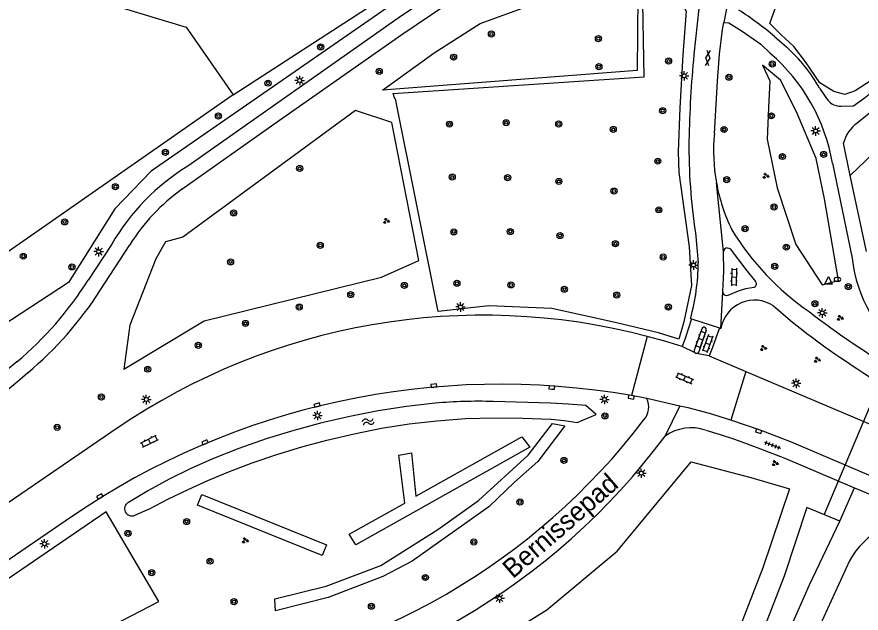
# Model space of a CAD drawing. Extents: x 131000 to 133013, y 393000 to 396501.
# Drawn here: x 131381.1 to 131491.8, y 394809 to 394887.2 of the extents above; entities that cross this region are included whole.
import ezdxf

# ---------------------------------------------------------------- set-up
doc = ezdxf.new("R2010")
doc.units = 0
for name, color, linetype in [('gg-afsc-erfafscheiding', 7, 'Continuous'), ('gg-afsc-hekwerk', 7, 'Continuous'), ('gg-anno-openbare ruimte label', 7, 'Continuous'), ('gg-knt-bovenkant onderkant talud', 7, 'Continuous'), ('gg-knt-verharding', 7, 'Continuous'), ('gg-knt-verharding nz', 7, 'Continuous'), ('gg-kntw-bovenkant insteek waterloop', 7, 'Continuous'), ('gg-kwrk-duiker nz buis', 7, 'Continuous'), ('gt-grn-groengrens', 7, 'Continuous'), ('gt-grn-vlakafsluiter', 7, 'Continuous'), ('gt-grn-weggrens', 7, 'Continuous'), ('gt-symb-boom', 7, 'Continuous'), ('gt-symb-brandkraan', 7, 'Continuous'), ('gt-symb-gesloten verharding', 7, 'Continuous'), ('gt-symb-groenvak', 7, 'Continuous'), ('gt-symb-klinker verharding', 7, 'Continuous'), ('gt-symb-kolk', 7, 'Continuous'), ('gt-symb-lichtmast', 7, 'Continuous'), ('gt-symb-tegel verharding', 7, 'Continuous'), ('gt-symb-waterafsluiter', 7, 'Continuous'), ('gt-symb-watersymbool', 7, 'Continuous')]:
    doc.layers.add(name, color=color, linetype=linetype)

# ---------------------------------------------------------------- blocks, each defined once
blk = doc.blocks.new('gt0-BOOM')
at = {"layer": 'gt-symb-boom'}
for radius in [0.4, 0.2]:
    blk.add_circle((0, 0), radius, dxfattribs=at)
blk = doc.blocks.new('gt0-LMAST')
at = {"layer": 'gt-symb-lichtmast'}
for p, q in [((-0.18, 0.17), (-0.45, 0.44)), ((-0.01, 0.25), (-0.01, 0.62)), ((0.17, 0.17), (0.44, 0.44)), ((-0.26, 0), (-0.63, 0)), ((-0.18, -0.18), (-0.45, -0.45)), ((-0.01, -0.25), (-0.01, -0.63)), ((0.44, -0.45), (0.17, -0.18)), ((0.24, 0), (0.62, 0))]:
    blk.add_line(p, q, dxfattribs=at)
blk.add_circle((-0.01, 0), 0.25, dxfattribs=at)
blk = doc.blocks.new('gt0-GESVH1')
at = {"layer": 'gt-symb-gesloten verharding'}
for p, q in [((-0.99, -0.26), (0.01, 0.24)), ((0.01, -0.26), (-0.99, 0.24)), ((0.01, 0.24), (1.01, -0.26)), ((1.01, 0.24), (0.01, -0.26))]:
    blk.add_line(p, q, dxfattribs=at)
blk = doc.blocks.new('gt0-GRVAK')
at = {"layer": 'gt-symb-groenvak'}
for p, q in [((-0.11, 0.19), (-0.23, 0.24)), ((-0.18, 0.15), (0.09, 0.15)), ((-0.09, 0.21), (-0.16, 0.32)), ((-0.05, 0.21), (-0.05, 0.39)), ((0, 0.21), (0.06, 0.32)), ((0.02, 0.19), (0.13, 0.24)), ((0.26, -0.05), (0.2, 0.06)), ((0.31, -0.05), (0.31, 0.13)), ((0.35, -0.05), (0.41, 0.06)), ((-0.24, -0.23), (-0.36, -0.18)), ((-0.32, -0.26), (-0.05, -0.26)), ((-0.23, -0.21), (-0.29, -0.09)), ((-0.18, -0.2), (-0.18, -0.02)), ((-0.14, -0.21), (-0.07, -0.09)), ((-0.12, -0.23), (0, -0.18)), ((0.24, -0.07), (0.12, -0.02)), ((0.17, -0.11), (0.44, -0.11)), ((0.37, -0.07), (0.49, -0.02))]:
    blk.add_line(p, q, dxfattribs=at)
blk = doc.blocks.new('gt0-KOLK')
at = {"layer": 'gt-symb-kolk'}
blk.add_lwpolyline([(0, 0), (0.37, 0), (0.37, 0.4), (-0.38, 0.4), (-0.38, 0), (0, 0)], dxfattribs=at)
blk = doc.blocks.new('gt0-KL1')
at = {"layer": 'gt-symb-klinker verharding'}
for p, q in [((-1.15, 0.3), (1.15, 0.3)), ((-1, -0.3), (-1, 0.3)), ((-0.5, 0.3), (-0.5, 0.45)), ((0, -0.3), (0, 0.3)), ((0.5, 0.3), (0.5, 0.45)), ((1, -0.3), (1, 0.3)), ((-1.15, -0.3), (1.15, -0.3)), ((-0.5, -0.45), (-0.5, -0.3)), ((0.5, -0.45), (0.5, -0.3))]:
    blk.add_line(p, q, dxfattribs=at)
blk = doc.blocks.new('gt0-WAFSL')
at = {"layer": 'gt-symb-waterafsluiter'}
for p, q in [((-0.5, -0.33), (0, 0.67)), ((0, 0.67), (0.5, -0.33)), ((0.5, -0.33), (-0.5, -0.33))]:
    blk.add_line(p, q, dxfattribs=at)
blk = doc.blocks.new('gt0-BR')
at = {"layer": 'gt-symb-brandkraan'}
for centre, radius, start, end in [((-0.24, 0), 0.206, 107.5669, 252.4331), ((0.6, -2.66), 3, 106.892, 107.5669), ((0, -0.69), 0.938, 73.108, 106.892), ((-0.6, -2.66), 3, 72.4331, 73.108), ((0.24, 0), 0.206, 287.567, 72.4331), ((0.6, 2.66), 3, 252.4331, 253.108), ((0, 0.69), 0.938, 253.108, 286.8921), ((-0.6, 2.66), 3, 286.8921, 287.567)]:
    blk.add_arc(centre, radius, start, end, dxfattribs=at)
blk = doc.blocks.new('gt0-TEG1')
at = {"layer": 'gt-symb-tegel verharding'}
for p, q in [((-1.12, 0), (1.12, 0)), ((-0.9, -0.25), (-0.9, 0.25)), ((-0.45, -0.25), (-0.45, 0.25)), ((0, -0.25), (0, 0.25)), ((0.45, -0.25), (0.45, 0.25)), ((0.9, -0.25), (0.9, 0.25))]:
    blk.add_line(p, q, dxfattribs=at)
blk = doc.blocks.new('gt0-WA')
at = {"layer": 'gt-symb-watersymbool'}
for centre, start, end in [((-0.32, 0.02), 28.0725, 151.9275), ((0.43, 0.42), 208.0725, 331.9275), ((-0.32, -0.43), 28.0725, 151.9275), ((0.43, -0.03), 208.0725, 331.9275)]:
    blk.add_arc(centre, 0.425, start, end, dxfattribs=at)

msp = doc.modelspace()

# ---------------------------------------------------------------- linework, layer by layer
at = {"layer": 'gg-afsc-erfafscheiding'}
msp.add_lwpolyline([(131382.74, 394892.07), (131403.32, 394885.82), (131409.48, 394876.97)], dxfattribs=at)
at = {"layer": 'gg-afsc-hekwerk'}
for points in [[(131409.48, 394876.97), (131433.9, 394892.83), (131436.29, 394894.28), (131439.98, 394898.11), (131439.63, 394901.76), (131437.93, 394908.16)], [(131383.91, 394859.19), (131409.38, 394876.91), (131409.48, 394876.97)]]:
    msp.add_lwpolyline(points, dxfattribs=at)
at = {"layer": 'gg-knt-bovenkant onderkant talud'}
msp.add_line((131490.29, 394815.9), (131481.29, 394796.36), dxfattribs=at)
msp.add_arc((131499.9, 394810.49), 11.03, 88.3052, 150.6017, dxfattribs=at)
at = {"layer": 'gg-knt-verharding'}
for p, q in [((131470.52, 394888.26), (131469.88, 394882.22)), ((131480.47, 394884.58), (131482.05, 394883.2)), ((131486.37, 394877.83), (131487.1, 394876.74)), ((131489.2, 394875.47), (131490.8, 394875.51)), ((131493.76, 394875.23), (131491.29, 394873.26)), ((131490.39, 394866.39), (131489.5, 394870.6)), ((131488.06, 394867.99), (131490.62, 394855.54)), ((131492.49, 394856.41), (131490.39, 394866.39)), ((131470.09, 394858.85), (131470.46, 394854.93)), ((131393.57, 394857.38), (131390.48, 394852.68)), ((131392.03, 394851.28), (131395.93, 394857.31)), ((131480.34, 394849.3), (131482.56, 394847.38)), ((131469.59, 394847.59), (131468.77, 394845.17)), ((131469.43, 394847.64), (131469.59, 394847.59)), ((131469.59, 394847.59), (131473.24, 394846.41)), ((131473.24, 394846.41), (131472.32, 394843.82)), ((131473.24, 394846.41), (131473.43, 394846.35)), ((131463.78, 394845.3), (131461.7, 394837.53)), ((131468.77, 394845.17), (131468.34, 394843.97)), ((131472.32, 394843.82), (131471.9, 394842.74)), ((131470.04, 394843.13), (131470.2, 394843.07)), ((131471.9, 394842.74), (131476.68, 394840.71)), ((131381.14, 394841.97), (131375.18, 394837.09)), ((131476.68, 394840.71), (131474.71, 394834.34)), ((131463.71, 394837.16), (131461.7, 394837.53)), ((131468.06, 394836.17), (131463.71, 394837.16)), ((131466.12, 394832.24), (131468.06, 394836.17)), ((131394.29, 394833.26), (131300.6, 394769.27)), ((131490.93, 394825.46), (131500.23, 394821.51)), ((131388.31, 394821.67), (131304.05, 394764.12))]:
    msp.add_line(p, q, dxfattribs=at)
for points in [[(131436.71, 394890.81), (131431.13, 394887), (131403.53, 394867.61)], [(131402.78, 394864.57), (131415.57, 394873.63), (131431.62, 394884.85), (131439.27, 394890.04)], [(131472.57, 394871.87), (131472.97, 394878.74), (131473.24, 394882.28), (131473.62, 394885.53), (131473.79, 394886.44)], [(131473.79, 394886.44), (131474.46, 394886.4), (131476.22, 394885.31), (131478.65, 394883.58), (131479.91, 394882.39)], [(131474.25, 394856.91), (131474.46, 394856.86), (131474.65, 394856.75), (131476.7, 394854.05), (131477.97, 394852.5)], [(131473.69, 394851.17), (131473.8, 394853.78), (131473.75, 394856.38)], [(131477.89, 394851.78), (131477.77, 394851.71), (131476.63, 394851.51), (131475.67, 394851.24), (131474.34, 394850.65), (131474.16, 394850.63), (131473.99, 394850.67), (131473.85, 394850.76), (131473.72, 394850.95), (131473.69, 394851.17)], [(131470.93, 394846.3), (131469.93, 394843.47), (131469.93, 394843.28), (131470.04, 394843.13)], [(131471.49, 394846.12), (131470.52, 394843.28), (131470.4, 394843.12), (131470.2, 394843.07)], [(131468.34, 394843.97), (131466.07, 394844.67), (131463.78, 394845.3)], [(131378.35, 394837.04), (131381.54, 394839.65), (131382.59, 394840.55)], [(131476.68, 394840.71), (131510.2, 394826.5), (131512.36, 394825.7)], [(131474.71, 394834.34), (131471.93, 394835.18), (131469.12, 394835.93), (131468.06, 394836.17)], [(131509.6, 394819.96), (131482.66, 394831.43), (131478.72, 394832.97), (131474.71, 394834.34)], [(131471.43, 394833.02), (131473.35, 394832.45), (131475.23, 394831.82), (131478.07, 394830.79), (131481.79, 394829.34), (131490.93, 394825.46)]]:
    msp.add_lwpolyline(points, dxfattribs=at)
for centre, radius, start, end in [((131452.42, 394851.63), 43.27, 49.5822, 57.3432), ((131473.3, 394900.95), 30.88, 304.5159, 333.2522), ((131463.78, 394863.76), 24.64, 9.898, 49.1217), ((131467.54, 394867.1), 21.67, 29.6679, 47.9583), ((131621.09, 394867.8), 151.89, 174.5512, 178.8182), ((131489.13, 394877.71), 2.25, 205.5536, 271.9602), ((131494.09, 394869.44), 4.74, 126.341, 165.8723), ((131496.11, 394869.63), 23.65, 174.5726, 190.271), ((131545.54, 394870.28), 76.31, 179.5131, 188.6136), ((131419.05, 394842.54), 29.48, 121.7506, 149.7763), ((131496.1, 394869.63), 23.64, 190.2855, 205.9898), ((131417.7, 394843.63), 25.71, 125.4665, 147.8465), ((131505.52, 394878.1), 35.99, 211.5418, 235.2011), ((131474.29, 394856.38), 0.534, 93.9828, 179.9134), ((131443.23, 394855.03), 27.22, 344.2568, 359.8021), ((131509.86, 394857.85), 19.38, 186.833, 232.0434), ((131351.71, 394877.05), 45.79, 309.9989, 327.8448), ((131477.57, 394852.18), 0.511, 308.3148, 38.7083), ((131351.71, 394877.22), 47.95, 310.0985, 327.2461), ((131477.85, 394845.57), 4.48, 56.3437, 170.0595), ((131442.26, 394762.99), 85.08, 75.3466, 124.322), ((131552.89, 394936.24), 110.91, 232.2492, 239.607), ((131550.73, 394932.42), 109, 231.2843, 246.5713), ((131471.21, 394846.21), 0.295, 341.7262, 163.5541), ((131444.5, 394739.41), 99.62, 80.0583, 124.3366), ((131461.34, 394836.05), 2.62, 318.2828, 25.0074), ((131392.99, 394888.08), 88.52, 277.5934, 322.5882), ((131469.57, 394827.27), 6.05, 72.1138, 124.7331), ((131394.66, 394885.27), 88.99, 276.7582, 323.4186)]:
    msp.add_arc(centre, radius, start, end, dxfattribs=at)
at = {"layer": 'gg-knt-verharding nz'}
for p, q in [((131474.39, 394889.4), (131473.79, 394886.44)), ((131470.04, 394843.13), (131468.34, 394843.97)), ((131471.9, 394842.74), (131470.2, 394843.07))]:
    msp.add_line(p, q, dxfattribs=at)
at = {"layer": 'gg-kntw-bovenkant insteek waterloop'}
for points in [[(131435.98, 394836.55), (131432.23, 394836.13), (131428.51, 394835.55), (131424.8, 394834.81), (131421.13, 394833.96), (131417.45, 394832.97), (131413.82, 394831.86), (131410.22, 394830.61), (131406.68, 394829.21), (131403.87, 394827.95), (131401.12, 394826.58), (131398.41, 394825.11), (131395.76, 394823.55)], [(131396.61, 394821.87), (131398.51, 394822.68), (131401.02, 394823.99), (131403.58, 394825.24), (131406.16, 394826.41), (131408.79, 394827.5), (131411.98, 394828.71), (131415.21, 394829.82), (131418.48, 394830.82), (131421.78, 394831.71), (131425.35, 394832.54), (131428.94, 394833.25), (131432.56, 394833.82), (131436.2, 394834.24), (131439.93, 394834.52), (131443.68, 394834.62), (131447.42, 394834.59), (131451.16, 394834.44), (131452.88, 394834.26), (131454.59, 394834), (131457.08, 394835.06), (131455.7, 394836.24), (131453.42, 394836.42), (131451.13, 394836.54), (131443.56, 394836.77)], [(131489, 394821.08), (131484.7, 394822.86), (131481.71, 394813.86), (131477.86, 394803.96), (131473.43, 394795.02), (131469.73, 394787.96), (131468.12, 394785.09)], [(131470.79, 394782.63), (131478.53, 394797.99), (131485.02, 394812.74), (131489, 394821.08)]]:
    msp.add_lwpolyline(points, dxfattribs=at)
for centre, radius, start, end in [((131441.73, 394770.03), 66.76, 88.434, 94.9394), ((131396.19, 394822.71), 0.939, 116.838, 296.5649)]:
    msp.add_arc(centre, radius, start, end, dxfattribs=at)
at = {"layer": 'gg-kwrk-duiker nz buis'}
msp.add_line((131486.95, 394821.93), (131498.71, 394849.76), dxfattribs=at)
at = {"layer": 'gt-grn-groengrens'}
msp.add_line((131489, 394821.08), (131490.93, 394825.46), dxfattribs=at)
for points in [[(131504.19, 394915.32), (131506.35, 394909.82), (131508.18, 394901.77), (131508.42, 394895.18), (131506.42, 394884.79), (131502.55, 394878.06), (131497.47, 394873.15), (131490.39, 394866.39)], [(131437.93, 394908.16), (131446.28, 394906.04), (131449.83, 394904.97), (131447.59, 394901.28), (131445.87, 394899.35), (131431.25, 394889.51), (131398.75, 394866.95), (131393.97, 394862), (131387.89, 394852.36), (131359.36, 394833.7)], [(131494.26, 394904.32), (131499.53, 394908.69), (131499.71, 394908.51), (131500.37, 394906.54), (131501.32, 394901.93), (131502.1, 394897.37), (131502.28, 394894.08), (131501.5, 394890.85), (131499.71, 394887.01), (131497.79, 394883.66), (131495.88, 394881.32), (131493.24, 394878.93), (131491.02, 394877.49), (131489.65, 394877.01), (131488.21, 394877.37), (131486.41, 394878.51), (131484.5, 394881.26), (131483, 394883.3), (131481.27, 394884.86), (131479.83, 394886.29), (131481.68, 394891.5), (131485.46, 394897.19), (131489.89, 394900.91), (131494.26, 394904.32)], [(131436.36, 394848.56), (131430.77, 394876.41), (131430.67, 394876.41), (131430.46, 394877.13), (131463.38, 394879.31), (131463.17, 394891.42), (131466.38, 394890.08), (131468.35, 394888.94), (131468.87, 394887.9), (131468.45, 394882.21), (131468.04, 394875.27), (131467.83, 394869.47), (131467.93, 394866.78), (131469.28, 394857.05), (131469.59, 394851.98), (131468.56, 394847.21), (131467.93, 394844.93), (131465.24, 394845.76), (131459.55, 394847.11), (131451.27, 394848.97), (131442.99, 394849.28), (131436.36, 394848.56)], [(131462.52, 394889.99), (131462.46, 394880.13), (131429.06, 394877.58), (131435.85, 394882.46), (131441.89, 394886.28), (131448.4, 394888.66), (131457.39, 394890.25), (131462.52, 394889.99)], [(131488.85, 394852.63), (131487, 394863.31), (131485.9, 394868.62), (131483.32, 394874.73), (131481.26, 394878.86), (131478.9, 394880.85), (131479.86, 394878.77), (131479.67, 394875.23), (131479.49, 394871.14), (131480.78, 394864.77), (131483.27, 394857.32), (131486.68, 394852.05), (131488.85, 394852.63)], [(131395.16, 394840.99), (131405.67, 394847.33), (131428.94, 394853.07), (131433.83, 394855.23), (131430.31, 394873.32), (131425.55, 394874.88), (131402.89, 394858.29), (131400.61, 394857.67), (131399.36, 394855.44), (131395.95, 394846.77), (131395.16, 394840.99)], [(131414.94, 394810.78), (131414.96, 394810.89), (131421.68, 394812.56), (131428.83, 394815.28), (131436.3, 394819.98), (131441.67, 394823.81), (131448.18, 394829.75), (131451.34, 394833.87), (131452.97, 394833.58), (131449.42, 394828.89), (131446.36, 394826.2), (131443.01, 394822.95), (131432.95, 394815.86), (131429.12, 394813.85), (131421.93, 394811.07), (131415.04, 394809.34), (131414.94, 394810.78)], [(131431.99, 394823.43), (131431.23, 394829.75), (131432.85, 394830.04), (131433.43, 394824.38), (131447.32, 394832.14), (131448.37, 394830.8), (131425.57, 394817.96), (131424.71, 394819.4), (131431.99, 394823.43)], [(131438.38, 394801.87), (131450.59, 394809.46), (131459.83, 394817.16), (131469.54, 394828.84), (131477.37, 394826.82), (131482.4, 394825.3), (131478.91, 394814.95), (131475.17, 394805.29)], [(131404.8, 394823.18), (131405.37, 394824.57), (131421.74, 394817.96), (131421.18, 394816.57), (131404.8, 394823.18)], [(131311.04, 394765.96), (131315.22, 394759.87), (131340.79, 394777.84), (131364.15, 394792.1), (131399.76, 394810.57), (131392.83, 394822.29), (131379.88, 394813.43), (131355.31, 394796.3), (131337.65, 394784.09), (131311.04, 394765.96)]]:
    msp.add_lwpolyline(points, dxfattribs=at)
at = {"layer": 'gt-grn-vlakafsluiter'}
msp.add_lwpolyline([(131355.54, 394839.5), (131361.32, 394843.5), (131383.91, 394859.19)], dxfattribs=at)
at = {"layer": 'gt-grn-weggrens'}
for p, q in [((131473.75, 394856.38), (131472.84, 394865.41)), ((131473.43, 394846.35), (131473.69, 394851.17))]:
    msp.add_line(p, q, dxfattribs=at)

# ---------------------------------------------------------------- block references
at = {"layer": 'gt-symb-boom'}
for p in [(131443.35, 394884.92), (131457.37, 394884.31), (131420.96, 394883.24), (131438.38, 394881.89), (131466.57, 394881.37), (131480.15, 394880.99), (131428.64, 394880.02), (131457.43, 394880.65), (131474.48, 394879.26), (131414.06, 394878.48), (131465.79, 394874.87), (131407.56, 394874.18), (131437.85, 394873.11), (131445.28, 394873.29), (131452.17, 394873.13), (131480.04, 394874.2), (131459.31, 394872.42), (131473.85, 394872.41), (131400.61, 394869.42), (131481.49, 394868.87), (131486.89, 394869.14), (131465.16, 394868.26), (131418.21, 394867.31), (131438.21, 394866.17), (131445.47, 394866.1), (131452.18, 394865.6), (131474.19, 394865.84), (131394.06, 394864.91), (131459.41, 394864.34), (131480.4, 394862.26), (131409.55, 394861.48), (131465.29, 394861.88), (131387.41, 394860.3), (131438.42, 394858.99), (131445.82, 394859.04), (131476.6, 394859.41), (131452.34, 394858.51), (131420.91, 394857.23), (131459.6, 394857.43), (131482, 394856.99), (131381.98, 394855.81), (131465.86, 394855.7), (131388.36, 394854.4), (131409.15, 394855.06), (131480.49, 394854.48), (131438.82, 394852.26), (131431.93, 394851.97), (131445.91, 394852.04), (131452.92, 394851.48), (131490.13, 394851.83), (131424.91, 394850.78), (131459.77, 394850.71), (131418.15, 394849.14), (131466.54, 394849.13), (131485.75, 394849.57), (131411.11, 394846.99), (131404.91, 394844.13), (131398.3, 394841), (131392.23, 394837.36), (131458.22, 394834.88), (131386.42, 394833.38), (131452.85, 394829.04), (131447.08, 394823.6), (131403.38, 394821.03), (131395.71, 394819.48), (131441.04, 394818.35), (131406.47, 394815.84), (131398.82, 394814.34), (131434.69, 394813.7), (131409.61, 394810.54), (131427.62, 394809.94)]:
    msp.add_blockref('gt0-BOOM', p, dxfattribs=at)
at = {"layer": 'gt-symb-brandkraan'}
msp.add_blockref('gt0-BR', (131488.7, 394852.76), dxfattribs=at)
at = {"layer": 'gt-symb-gesloten verharding', "rotation": 84.08992967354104}
msp.add_blockref('gt0-GESVH1', (131471.7, 394881.77), dxfattribs=at)
at = {"layer": 'gt-symb-groenvak'}
for p in [(131479.3, 394866.33), (131429.56, 394860.42), (131489.04, 394847.71), (131478.98, 394843.76), (131486.03, 394842.23), (131480.52, 394828.67), (131411.05, 394818.55)]:
    msp.add_blockref('gt0-GRVAK', p, dxfattribs=at)
at = {"layer": 'gt-symb-klinker verharding'}
for p, rotation in [((131475.14, 394853.08), -91.203034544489), ((131470.77, 394844.9), 70.18818811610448), ((131471.71, 394844.34), -109.93904791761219), ((131468.66, 394839.81), -23.025492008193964), ((131398.52, 394831.56), 26.36005820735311)]:
    msp.add_blockref('gt0-KL1', p, dxfattribs=dict(at, rotation=rotation))
at = {"layer": 'gt-symb-kolk'}
for p, rotation in [((131435.81, 394838.64), 4.41628344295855), ((131451.26, 394838.39), -4.530520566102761), ((131461.7, 394837.53), 171.6591331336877), ((131420.55, 394836.1), 14.591956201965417), ((131478.45, 394833.06), 160.4964267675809), ((131405.88, 394831.23), 23.25875933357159), ((131392.12, 394824.15), 31.258485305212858)]:
    msp.add_blockref('gt0-KOLK', p, dxfattribs=dict(at, rotation=rotation))
at = {"layer": 'gt-symb-lichtmast'}
for p in [(131418.22, 394878.84), (131468.62, 394879.45), (131485.85, 394872.22), (131391.87, 394856.41), (131469.85, 394854.65), (131439.3, 394849.15), (131486.72, 394848.38), (131483.3, 394839.15), (131398.12, 394837.02), (131458.17, 394837.04), (131420.55, 394834.94), (131463, 394827.38), (131384.78, 394818.12), (131444.42, 394811)]:
    msp.add_blockref('gt0-LMAST', p, dxfattribs=at)
at = {"layer": 'gt-symb-tegel verharding', "rotation": -20.737148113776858}
msp.add_blockref('gt0-TEG1', (131480.19, 394831.06), dxfattribs=at)
at = {"layer": 'gt-symb-waterafsluiter'}
msp.add_blockref('gt0-WAFSL', (131487.53, 394852.48), dxfattribs=at)
at = {"layer": 'gt-symb-watersymbool', "rotation": 17.456558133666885}
msp.add_blockref('gt0-WA', (131427.15, 394834.1), dxfattribs=at)

# ---------------------------------------------------------------- texts
at = {"layer": 'gg-anno-openbare ruimte label'}
msp.add_text('Bernissepad', height=2.5, rotation=41, dxfattribs=at).set_placement((131446.16, 394813.46))

doc.saveas('drawing.dxf')
